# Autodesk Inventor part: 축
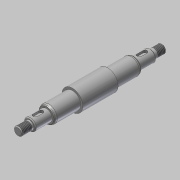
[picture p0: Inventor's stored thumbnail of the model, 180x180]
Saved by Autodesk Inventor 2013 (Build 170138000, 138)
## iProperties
Created: 2020-05
Part Number: 축
Material: 강철, 연강
Document SubType Name: Modeling
Designer: mduedu
Density: 1 g/cm^3
Author: mduedu
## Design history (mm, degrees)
sketch "스케치1"
  geometry: L1 (0, 0)-(21, 0); L2 (21, 0)-(21, 12.5); L3 (21, 12.5)-(0, 12.5); L4 (0, 12.5)-(0, 0); L5 (21, 0)-(52, 0); L6 (52, 0)-(52, 10); L7 (52, 10)-(21, 10); L8 (21, 10)-(21, 0); L9 (52, 0)-(72, 0); L10 (72, 0)-(72, 7); L11 (72, 7)-(52, 7); L12 (52, 7)-(52, 0); L13 (72, 0)-(86, 0); L14 (86, 0)-(86, 5); L15 (86, 5)-(72, 5); L16 (72, 5)-(72, 0); L17 (0, 0)-(-21, 0); L18 (-21, 0)-(-21, 12.5); L19 (-21, 12.5)-(0, 12.5); L20 (-21, 0)-(-52, 0); L21 (-52, 0)-(-52, 10); L22 (-52, 10)-(-21, 10); L23 (-21, 10)-(-21, 0); L24 (-52, 0)-(-72, 0); L25 (-72, 0)-(-72, 7); L26 (-72, 7)-(-52, 7); L27 (-52, 7)-(-52, 0); L28 (-72, 0)-(-86, 0); L29 (-86, 0)-(-86, 5); L30 (-86, 5)-(-72, 5); L31 (-72, 5)-(-72, 0)
  constraints: 62 end point, 11 symmetric about line, 8 parallel, 4 horizontal, 4 perpendicular
  dimensions: "d0" = 172 distance between parallel lines of L14 L29; "d2" = 25 diameter of L3 L1; "d3" = 20 diameter of L7 L5; "d4" = 14 diameter of L11 L9; "d5" = 10 diameter of L15 L13; "d6" = 42 distance of L2.end L18.end; "d7" = 31 distance of L6.end L7.end; "d8" = 20 distance of L10.end L11.end; "d9" = 14 distance of L14.end L15.end (derived)
revolve "회전1" sketch "스케치1" stored, may be unused: angle "d10" = 90 deg
sketch "스케치2"
  geometry: L1 (72, -5)-(72, -7) reference; L2 (72, -7)-(52, -7) reference; L3 (52, -7)-(52, -10) reference; L4 (52, -10)-(21, -10) reference; L5 (21, -10)-(21, -12.5) reference; L6 (21, -12.5)-(-21, -12.5) reference; L7 (-21, -12.5)-(-21, -10) reference; L8 (-21, -10)-(-52, -10) reference; L9 (-52, -10)-(-52, -7) reference; L10 (-52, -7)-(-72, -7) reference; L11 (-72, -7)-(-72, -5) reference; L12 (-72, -5)-(-86, -5) reference; L13 (-86, -5)-(-86, 5) reference; L14 (-86, 5)-(-72, 5) reference; L15 (-72, 5)-(-72, 7) reference; L16 (-72, 7)-(-52, 7) reference; L17 (-52, 7)-(-52, 10) reference; L18 (-52, 10)-(-21, 10) reference; L19 (-21, 10)-(-21, 12.5) reference; L20 (-21, 12.5)-(21, 12.5) reference; L21 (21, 12.5)-(21, 10) reference; L22 (21, 10)-(52, 10) reference; L23 (52, 10)-(52, 7) reference; L24 (52, 7)-(72, 7) reference; L25 (72, 7)-(72, 5) reference; L26 (72, 5)-(86, 5) reference; L27 (86, 5)-(86, -5) reference; L28 (86, -5)-(72, -5) reference; L29 (-86, 0)-(86, 0); L30 (0, -12.5)-(0, 12.5); L31 (-52, 8.85)-(-50.008, 10); L32 (-50.008, 10)-(-52, 10); L33 (-52, 10)-(-52, 8.85); 1 further point
  constraints: 10 end point, 4 midpoint, 2 collinear, 2 point on line
  dimensions: "d11" = 17.7 diameter of L31.start L29; "d12" = 30 deg angle of L31 L32
revolve "회전2" sketch "스케치2" stored, may be unused: angle "d13" = 90 deg
fillet "모깎기1" dims "d14" = 4, "d15" = 0.5
node "작업 평면1"
sketch "스케치3"
  geometry: L1 (-6, 2.5)-(6, 2.5); L2 (6, 2.5)-(6, -2.5); L3 (6, -2.5)-(-6, -2.5); L4 (-6, -2.5)-(-6, 2.5); L5 (-10, 8.561)-(-10, -8.561) reference; 2 further points
  constraints: 8 end point, 2 parallel, 1 horizontal, 1 horizontal alignment, 1 midpoint, 1 perpendicular
  dimensions: "d16" = 5 distance of L1.end L2.end; "d18" = 4 distance between parallel lines of L4 L5; "d19" = 12 distance of L1.start L1.end
extrude "돌출1" cut sketch "스케치3" distance "d20" = 3; taper "d21" = 0 deg
fillet "모깎기2" dims "d22" = 2.5
fillet "모깎기3" dims "d23" = 2.5
feature "스레드1" dims "d24" = 12, "d25" = 0
feature "스레드2" dims "d26" = 10, "d27" = 0
chamfer "모따기1" distance "d28" = 1; stored, may be unused: second distance "d29" = 2, angle "d30" = 45 deg
chamfer "모따기2" distance "d31" = 1; stored, may be unused: second distance "d32" = 2, angle "d33" = 45 deg
node "솔리드1"
mirror "대칭1"
mirror "대칭2"
node "절단 모서리 투영1"
